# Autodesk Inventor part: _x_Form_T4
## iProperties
Created: 2005-11
Part Number: _x_Form_T4
Document SubType Name: Modeling
Designer: IMA/Frank
Manufacturer: Standard
Standards Organization: Custom
Author: IMA/Frank
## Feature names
1. Trennen1
2. Trennen2
3. Trennen3
4. Abgeleiteter Körper1 [Tagging]
